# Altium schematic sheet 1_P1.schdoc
size 431 x 309 mm; Symbol: Sheet-Symbol_A4; Device: Sheet-Symbol_A4; Company: 嘉立创EDA; Version: V1.0; Page Size: A4; @Project Name: New Project_2023-10-27_14-14-08; @Page Count: 1; @Update Date: 2023-11-07; @Create Date: 2023-11-07; @Schematic Name: Schematic1; @Page No: 1; @Page Name: P1
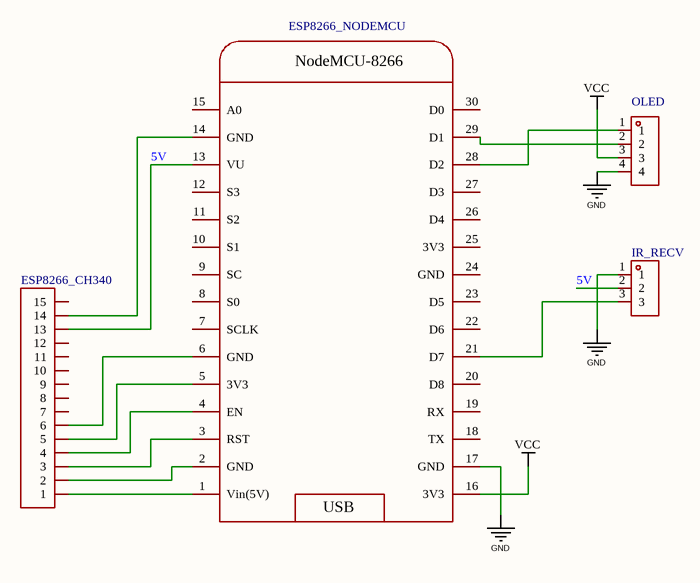
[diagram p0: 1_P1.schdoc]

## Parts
ESP8266_CH340  HDR-F_2.54_1x15P  [HDR-TH_15P-P2.54-V-F-1]  (value not drawn)
ESP8266_NODEMCU  NodeMCU8266  [nodemcu8266]  (value not drawn)
IR_RECV  HDR-F_2.54_1x3P  [HDR-TH_3P-P2.54-V-F]  (value not drawn)
OLED  HDR-F_2.54_1x4P  [HDR-TH_4P-P2.54-V-F]  (value not drawn)

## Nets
GND: ESP8266_NODEMCU.17(GND) IR_RECV.1 OLED.4
VCC: ESP8266_NODEMCU.16(3V3) OLED.3
5V: ESP8266_CH340.13 ESP8266_NODEMCU.13(VU) IR_RECV.2
NetESP8266_CH340_1: ESP8266_CH340.1 ESP8266_NODEMCU.1(Vin(5V))
NetESP8266_CH340_2: ESP8266_CH340.2 ESP8266_NODEMCU.2(GND)
NetESP8266_CH340_3: ESP8266_CH340.3 ESP8266_NODEMCU.3(RST)
NetESP8266_CH340_4: ESP8266_CH340.4 ESP8266_NODEMCU.4(EN)
NetESP8266_CH340_5: ESP8266_CH340.5 ESP8266_NODEMCU.5(3V3)
NetESP8266_CH340_6: ESP8266_CH340.6 ESP8266_NODEMCU.6(GND)
NetESP8266_CH340_14: ESP8266_CH340.14 ESP8266_NODEMCU.14(GND)
NetESP8266_NODEMCU_21: ESP8266_NODEMCU.21(D7) IR_RECV.3
NetESP8266_NODEMCU_28: ESP8266_NODEMCU.28(D2) OLED.1
NetESP8266_NODEMCU_29: ESP8266_NODEMCU.29(D1) OLED.2

Not connected (* = marked no-connect by the designer): ESP8266_CH340 7 8 9 10 11 12 15; ESP8266_NODEMCU 7(SCLK) 8(S0) 9(SC) 10(S1) 11(S2) 12(S3) 15(A0) 18(TX) 19(RX) 20(D8) 22(D6) 23(D5) 24(GND) 25(3V3) 26(D4) 27(D3) 30(D0)

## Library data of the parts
ESP8266_CH340 = HDR-F_2.54_1x15P: Convert to PCB: yes
ESP8266_NODEMCU = NodeMCU8266: Convert to PCB: yes
IR_RECV = HDR-F_2.54_1x3P: Manufacturer: XFCN(兴飞); Symbol: PM254V-11-03-H85; Convert to PCB: yes
OLED = HDR-F_2.54_1x4P: Manufacturer: BOOMELE(博穆精密); Symbol: 2.54-1*4P母; Convert to PCB: yes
